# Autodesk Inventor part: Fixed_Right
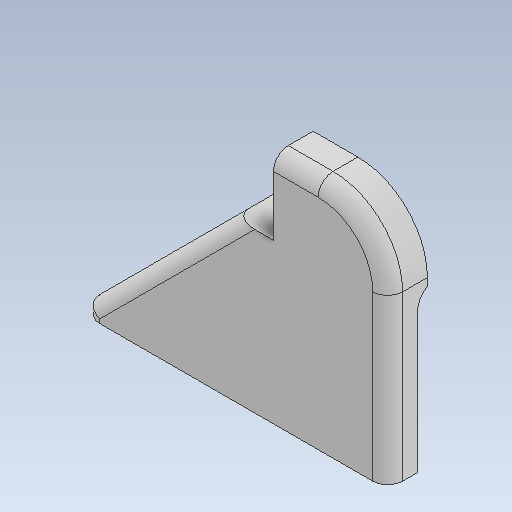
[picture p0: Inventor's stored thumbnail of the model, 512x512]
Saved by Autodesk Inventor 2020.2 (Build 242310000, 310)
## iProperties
Created: 2019-12
Part Number: Fixed_Right
Material: Generic
Document SubType Name: Modeling
Designer: Patrick Everitt
Density: 1 g/cm^3
Appearance: Default
Description: 1x6 CRS 8 Lg
Author: Patrick Everitt
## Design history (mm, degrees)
sketch "Sketch1"
  geometry: L1 (25.4, -50.8)-(25.4, -3.175); L2 (25.4, -50.8)-(73.025, -50.8); L3 (25.4, -3.175)-(53.975, -3.175); L4 (98.425, -47.625)-(98.425, -152.4); L5 (25.4, -50.8)-(0, -50.8); L6 (98.425, -152.4)-(-95.25, -152.4); L7 (0, -50.8)-(-95.25, -146.05); L8 (-95.25, -152.4)-(-95.25, -146.05); A1 r 44.45 centre (53.975, -47.625) between (98.425, -47.625) and (53.975, -3.175); 2 further points
  constraints: 16 end point, 3 horizontal, 3 perpendicular, 2 point on circle, 2 point on line, 2 tangent, 1 centre point, 1 parallel, 1 vertical
  dimensions: "d6" = 47.625 distance of L1.start L1.end; "d7" = 90 deg angle of L2 L1 (derived); "d8" = 73.025 distance of L1.end point (98.425, -3.175); "d9" = 90 deg angle of L1 L3 (derived); "d11" = 90 deg angle of L3 L4 (derived); "d14" = 25.4 horizontal distance of point (0, 0) L1.end; "d17" = 101.6 vertical distance of L6.end L5.end; "d18" = 44.45 radius of A1 (derived); "d23" = 45 deg angle of L4 L7; "d24" = 3.175 distance from line of point (0, 0) L3; "d42" = 6.35 distance of L6.end L7.end; "d43" = 193.675 distance between parallel lines of L4 L8
extrude "Extrusion1" new body sketch "Sketch1" distance "d25" = 25.4; taper "d26" = 0 deg
sketch "Sketch2"
  geometry: L1 (0, 0)-(-25.4, 0) reference; L2 (-6.35, 0)-(-6.35, 88.9); L3 (0, 101.6)-(0, 0) reference; L4 (-6.35, 0)-(82.55, 0); L5 (6.35, 101.6)-(19.05, 101.6); L6 (19.05, 101.6)-(19.05, 0); L7 (19.05, 0)-(-6.35, 0); L8 (0, 149.225)-(0, 104.775) reference; A1 r 12.7 centre (6.35, 88.9) between (6.35, 101.6) and (-6.35, 88.9); 4 further points
  constraints: 10 end point, 3 perpendicular, 2 point on circle, 2 point on line, 2 tangent, 1 centre point, 1 collinear, 1 horizontal, 1 parallel
  dimensions: "d28" = 101.6 distance of L2.start point (-6.35, 101.6); "d29" = 90 deg angle of L4 L2 (derived); "d30" = 25.4 distance of point (-6.35, 101.6) L5.end; "d31" = 90 deg angle of L2 L5 (derived); "d32" = 12.7 radius of A1 (derived); "d40" = 19.05 distance from line of L5.end L8
extrude "Extrusion2" cut sketch "Sketch2" extent not by distance; stored distance "d33" = 0; taper "d34" = 0 deg
fillet "Fillet1" dims "d44" = 9.525
sketch "Sketch4"
  geometry: L1 (193.675, 9.525)-(149.225, 9.525) reference; L2 (95.25, 9.525)-(0, 9.525) reference; L3 (193.675, 0)-(193.675, 9.525) reference; L4 (0, 0)-(0, 9.525) reference; 3 further points
  constraints: 2 point on line
  dimensions: "d52" = 38.1 distance from line of L3 point (155.575, 9.525); "d53" = 38.1 distance from line of L4 point (38.1, 9.525) (= d52)
hole "Hole1" sketch "Sketch4" at (155.575, 9.525), (38.1, 9.525) diameter "d45" = 7.7978; stored, may be unused: countersink angle "d49" = 82 deg, drill point angle "d51" = 118 deg; dims "d46" = 19.05, "d47" = 9.525, "d48" = 6.35, "d50" = 27.0002
body "Solid1"
